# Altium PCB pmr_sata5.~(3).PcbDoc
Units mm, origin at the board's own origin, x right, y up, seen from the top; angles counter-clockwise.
Board outline 135.05 x 99.92 mm, 2 copper layers (Top Layer, Bottom Layer); 2 components, 12 nets, 33 pads, 0 vias.
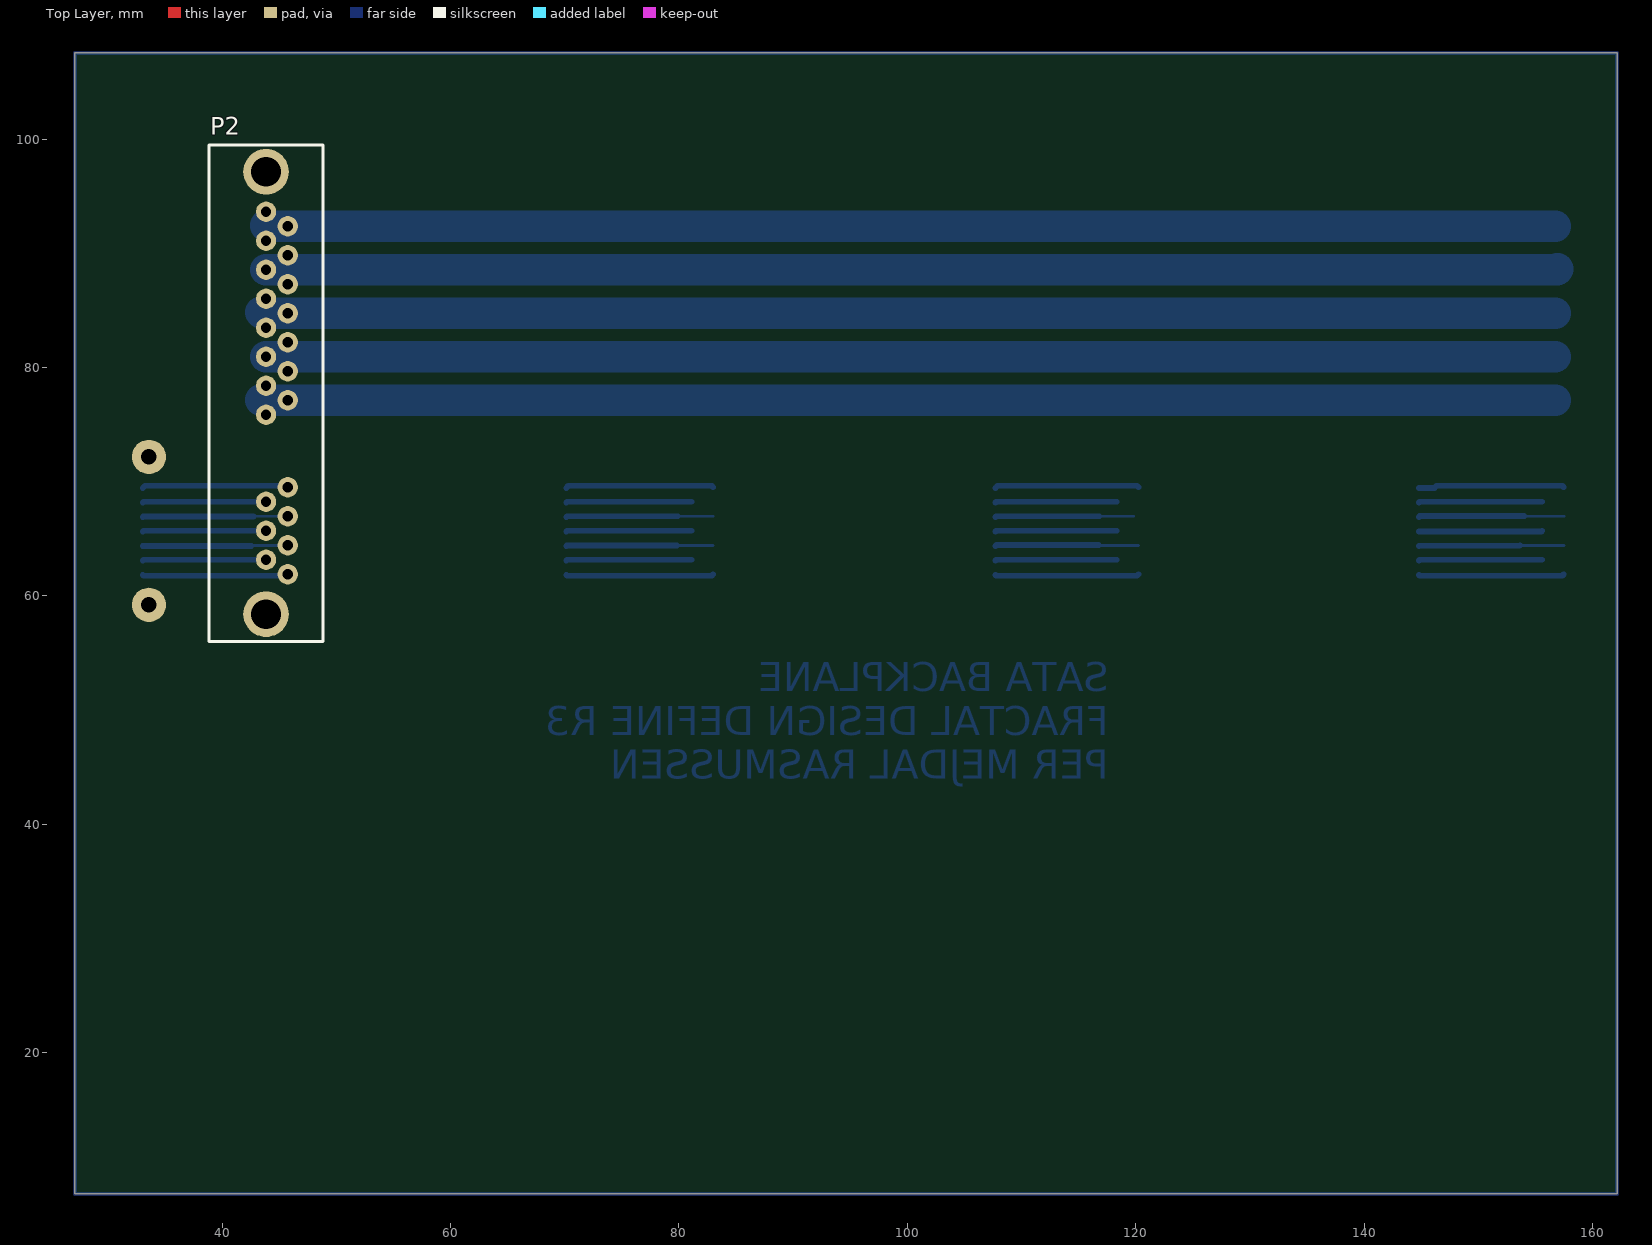
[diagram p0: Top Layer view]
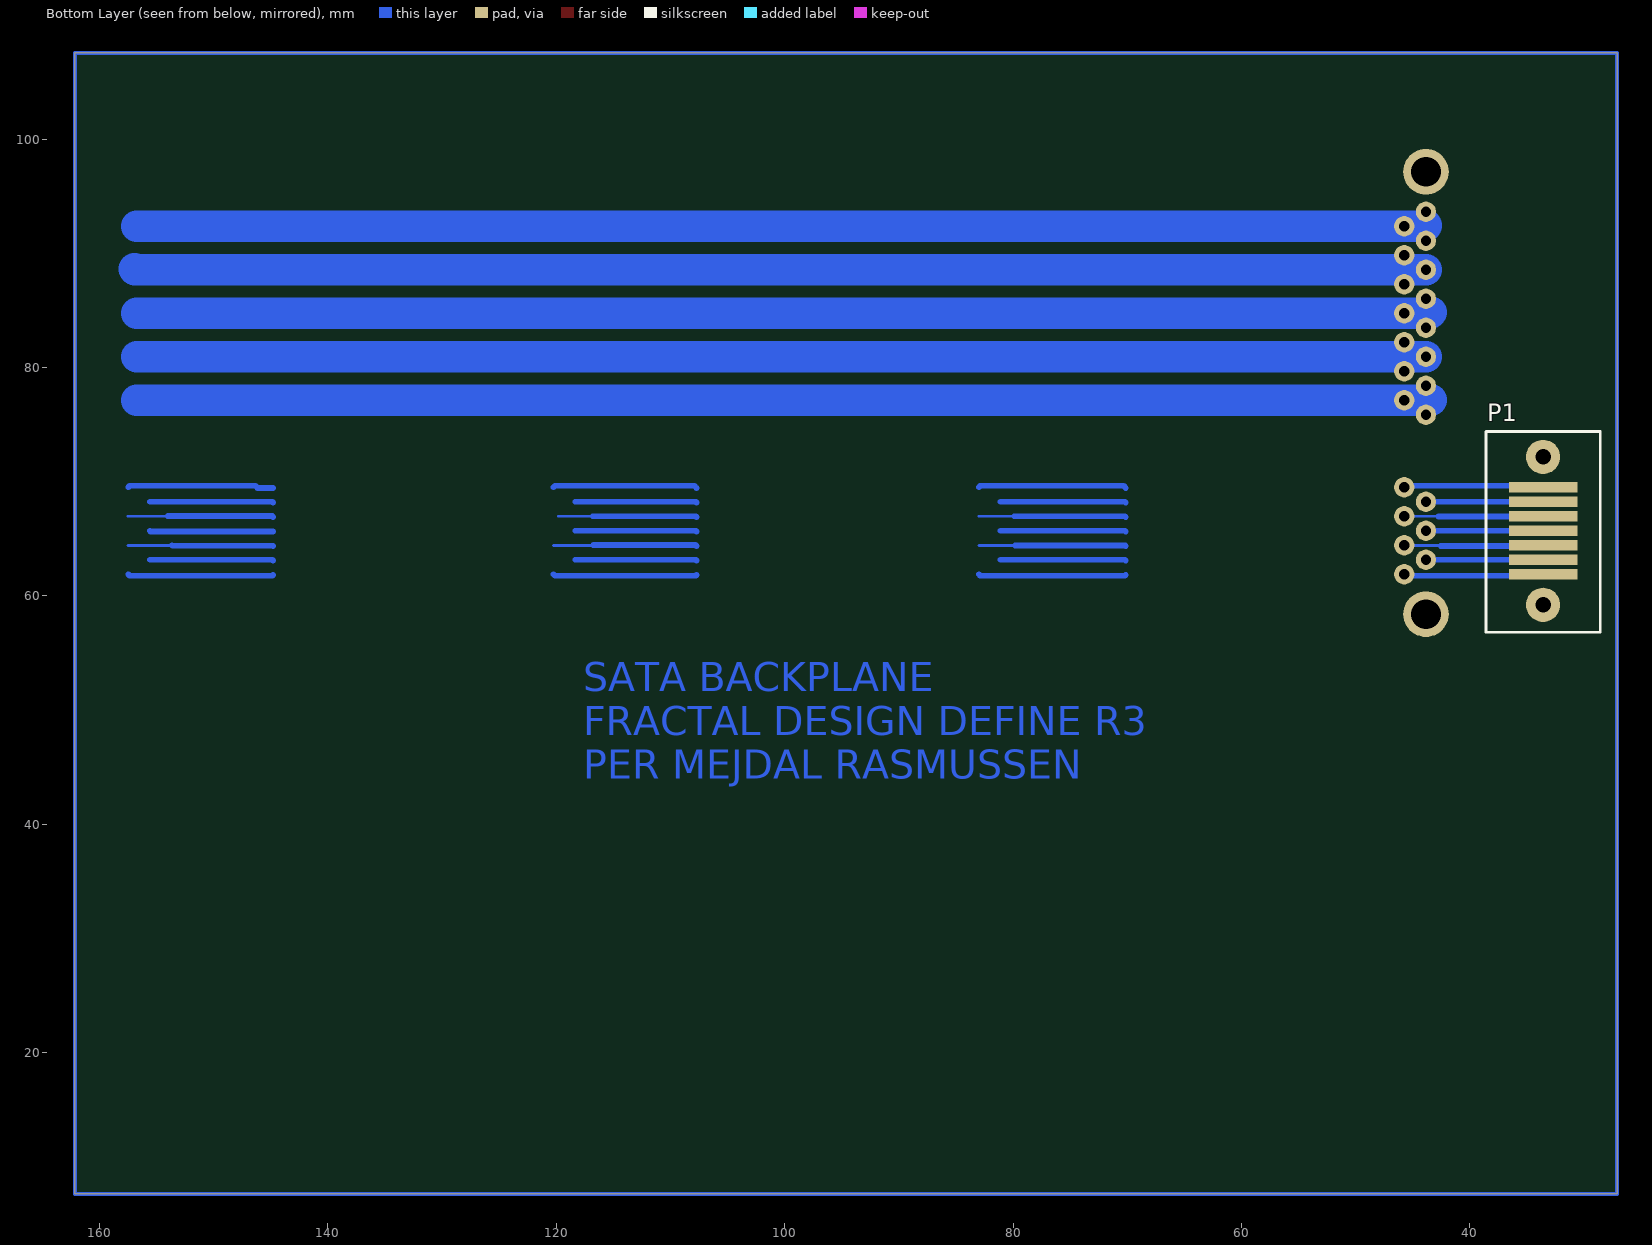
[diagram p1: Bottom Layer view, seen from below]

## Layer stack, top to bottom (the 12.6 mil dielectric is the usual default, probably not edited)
Top Solder: solder mask 0.0102, Solder Resist, Dk 3.5
Top Layer: signal copper 0.0356
Dielectric1: dielectric 0.32, FR-4, Dk 4.8
Bottom Layer: signal copper 0.0356
Bottom Solder: solder mask 0.0102, Solder Resist, Dk 3.5

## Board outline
27.102,7.62 162.154,7.62 162.154,107.544 27.102,107.544

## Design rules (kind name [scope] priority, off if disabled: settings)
Clearance [All] p1: gap=0.254
DiffPairsRouting [All] p1: maxlimit=0.254 minlimit=0.254 mostfreqgap=0.254 toplayer_minwidth=0.381 toplayer_maxwidth=0.381 toplayer_prefwidth=0.381 bottomlayer_minwidth=0.381 bottomlayer_maxwidth=0.381 bottomlayer_prefwidth=0.381 maxuncoupledlength=12.7
PolygonConnect [All] p1: connectstyle=Relief reliefconductorwidth=0.254 reliefentries=4 polygonreliefangle="90 Angle" airgapwidth=0.254
RoomDefinition pmr_sata_single [InComponentClass('pmr_sata_single')] p1 off: confinementstyle=ConfineIn formatcopy=TRUE lockcomponents=FALSE outline 192.278,29.464 184.912,29.464 184.912,40.386 192.278,40.386
RoutingVias [All] p1: holewidth=0.711 width=1.27 viastyle="Through Hole" minholewidth=0.711 minwidth=1.27 maxholewidth=0.711 maxwidth=1.27
SilkToSolderMaskClearance SilkscreenOverComponentPads [IsPad] p1: minsilkscreentomaskgap=0.254 clearancetoexposedcopper=TRUE
SolderMaskExpansion [All] p1: expansion=0.102
Width [All] p1: maxlimit=12.7 minlimit=0.254 preferedwidth=0.254
28 further rules are at their usual default settings.

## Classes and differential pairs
differential pair PAIR2: +PAIR2_P -PAIR2_N
differential pair PAIR1: +PAIR1_P -PAIR1_N

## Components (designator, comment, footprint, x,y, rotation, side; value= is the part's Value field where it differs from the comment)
P1 "SATA lille" "pmr_sata -lille" 33.579,59.207 r90 bottom
P2 "SATA STOR" pmr_sata 43.84,58.395 r90 top

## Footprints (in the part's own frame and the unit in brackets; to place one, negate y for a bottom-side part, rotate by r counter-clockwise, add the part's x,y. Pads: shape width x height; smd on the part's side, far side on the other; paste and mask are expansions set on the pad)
pmr_sata [mm]
  round 1.778 hole 0.9: P1(17.46,0) P2(18.73,-1.9) P3(20,0) P4(21.27,-1.9) P5(22.54,0) P6(23.81,-1.9) P7(25.08,0) P8(26.35,-1.9) P9(27.62,0) P10(28.89,-1.9) P11(30.16,0) P12(31.43,-1.9) P13(32.7,0) P14(33.97,-1.9) P15(35.24,0) S1(3.49,-1.9) S2(4.76,0) S3(6.03,-1.9) S4(7.3,0) S5(8.57,-1.9) S6(9.84,0) S7(11.11,-1.9)
  round 4 hole 2.6: S8(0,0) S8(38.74,0)
  silkscreen extent -2.4,-5 41.1,5
"pmr_sata -lille" [mm]
  rect 0.9x6 smd: S1(2.67,0) S2(3.94,0) S3(5.21,0) S4(6.48,0) S5(7.75,0) S6(9.02,0) S7(10.29,0)
  round 3 hole 1.35: S8(0,0) S8(12.96,0)
  silkscreen extent -2.4,-5 15.2,5

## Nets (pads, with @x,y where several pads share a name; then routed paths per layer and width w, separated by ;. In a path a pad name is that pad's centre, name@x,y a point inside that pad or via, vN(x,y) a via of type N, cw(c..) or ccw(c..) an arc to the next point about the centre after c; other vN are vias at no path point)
GND1: P2.P4 P2.P5 P2.P6 | length 112.9
  Bottom Layer w2.794: P2.P5 81.09,80.935 118.34,80.935 156.718,80.935
GND2: P2.P10 P2.P11 P2.P12 | length 113.1
  Bottom Layer w2.794: P2.P11 154.841,88.555 156.881,88.555 156.947,88.621
NetP1_S1: P1.S1 P2.S1 | length 12.8
  Bottom Layer w0.508: P1.S1@33.045,61.827 33.114,61.758 45.613,61.758 P2.S1
NetP1_S4: P1.S4 P2.S4 | length 10.8
  Bottom Layer w0.508: P1.S4@33.045,65.637 33.103,65.695 P2.S4
NetP1_S7: P1.S7 P2.S7 | length 12.8
  Bottom Layer w0.508: P1.S7@33.045,69.447 33.23,69.632 45.613,69.632 P2.S7
PAIR1_N: P1.S2 P2.S2 | length 10.8
  Bottom Layer w0.508: P1.S2@33.045,63.097 33.103,63.155 P2.S2
PAIR1_P: P1.S3 P2.S3 | length 12.7
  Bottom Layer w0.254: 42.545,64.364 42.606,64.425 P2.S3
  Bottom Layer w0.508: P1.S3@33.045,64.367 33.048,64.364 42.545,64.364
PAIR2_N: P1.S5 P2.S5 | length 13.4
  Bottom Layer w0.254: 42.748,66.954 42.758,66.965 P2.S5
  Bottom Layer w0.381: P2.S5@45.11,67.005 45.151,66.965 P2.S5
  Bottom Layer w0.508: P1.S5@33.045,66.907 33.093,66.954 42.748,66.954
PAIR2_P: P1.S6 P2.S6 | length 10.8
  Bottom Layer w0.508: P1.S6@33.045,68.177 33.103,68.235 P2.S6
VCC1: P2.P1 P2.P2 P2.P3 | length 113.9
  Bottom Layer w2.794: 43.383,77.165 43.424,77.125 P2.P2 82.99,77.125 119.741,77.125 ; 120.24,77.125 119.741,77.125 ; 156.741,77.125 119.741,77.125
VCC2: P2.P7 P2.P8 P2.P9 | length 113.4
  Bottom Layer w2.794: 43.383,84.836 43.475,84.745 P2.P8 82.99,84.745 120.24,84.745 156.741,84.745
VCC3: P2.P13 P2.P14 P2.P15 | length 113.5
  Bottom Layer w2.794: 43.815,92.431 43.881,92.365 P2.P14 82.99,92.365 120.24,92.365 ; 119.741,92.365 144.694,92.365 156.741,92.365
pads on no net: P1.S8 P2.S8
copper on no net: | length 719.9
  Bottom Layer w0.254: 79.807,64.414 79.817,64.425 82.99,64.425 ; 79.893,66.965 82.99,66.965 ; 116.764,64.425 120.24,64.425 ; 116.815,66.965 119.819,66.965 ; 153.645,64.425 157.49,64.425 ; 154.026,66.965 157.49,66.965
  Bottom Layer w0.381: 27.102,7.62 162.154,7.62 162.154,107.544 27.102,107.544 27.102,7.62
  Bottom Layer w0.508: 70.129,61.827 70.198,61.758 82.863,61.758 82.99,61.885 ; 70.129,63.097 70.187,63.155 81.09,63.155 ; 70.129,64.367 70.177,64.414 79.807,64.414 ; 70.129,65.637 70.187,65.695 81.09,65.695 ; 70.129,66.907 70.187,66.965 79.893,66.965 ; 70.129,68.177 70.187,68.235 81.09,68.235 ; 70.129,69.447 70.314,69.632 82.863,69.632 82.99,69.505 ; 107.721,61.827 107.79,61.758 120.113,61.758 120.24,61.885 ; 107.721,63.097 107.779,63.155 118.34,63.155 ; 107.721,64.367 107.795,64.44 116.749,64.44 116.764,64.425 ; 107.721,65.637 107.779,65.695 118.34,65.695 ; 107.721,66.907 107.779,66.965 116.815,66.965 ; 107.721,68.177 107.779,68.235 118.34,68.235 ; 107.721,69.447 107.906,69.632 120.113,69.632 120.24,69.505 ; 144.805,61.827 144.874,61.758 157.363,61.758 157.49,61.885 ; 144.805,63.097 144.863,63.155 155.59,63.155 ; 144.805,64.367 144.828,64.389 153.609,64.389 153.645,64.425 ; 144.805,65.637 155.532,65.637 155.59,65.695 ; 144.805,66.907 144.879,66.98 154.01,66.98 154.026,66.965 ; 144.805,68.177 144.863,68.235 155.59,68.235 ; 144.805,69.447 146.159,69.447 146.344,69.632 157.363,69.632 157.49,69.505

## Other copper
Bottom Layer:
  text "SATA BACKPLANE" at 117.653,51.638 h2.54
  text "FRACTAL DESIGN DEFINE R3" at 117.653,47.803 h2.54
  text "PER MEJDAL RASMUSSEN" at 117.653,43.967 h2.54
